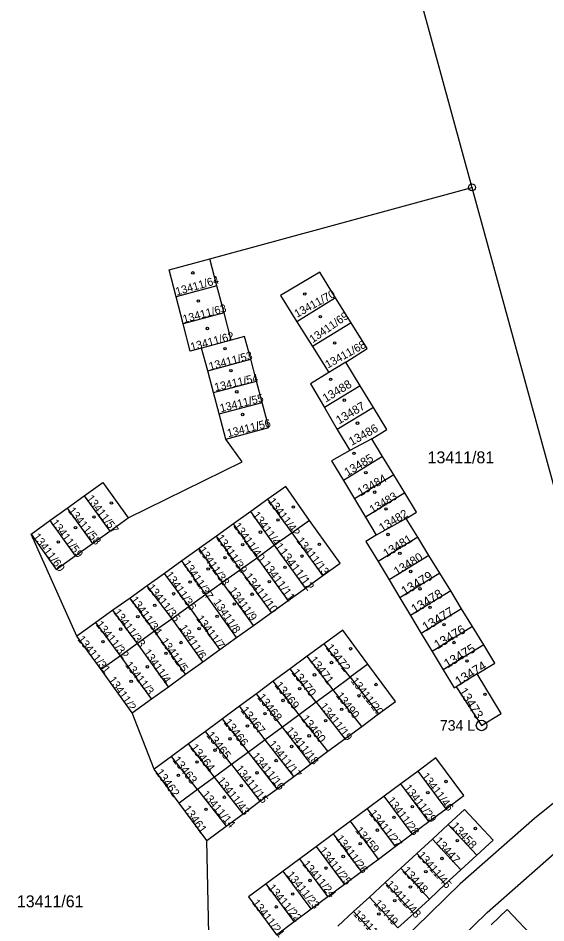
# Model space of a CAD drawing. Extents: x -821458 to -820266, y -1071458 to -1069826.
# Drawn here: x -820677.2 to -820602.1, y -1071105.6 to -1070976.8 of the extents above; entities that cross this region are included whole.
import ezdxf

# ---------------------------------------------------------------- set-up
doc = ezdxf.new("R2010")
doc.units = 0
for name, color, linetype in [('Vrstva 1', 7, 'Continuous'), ('Vrstva 13', 7, 'Continuous'), ('Vrstva 2', 7, 'Continuous'), ('Vrstva 5', 7, 'Continuous'), ('Vrstva 8', 7, 'Continuous')]:
    doc.layers.add(name, color=color, linetype=linetype)

msp = doc.modelspace()

# ---------------------------------------------------------------- linework, layer by layer
at = {"layer": 'Vrstva 1'}
for p, q in [((-820649.92, -1071011.03), (-820612.61, -1071000.86)), ((-820648.9, -1071014.88), (-820649.92, -1071011.03)), ((-820648.9, -1071014.88), (-820654.7, -1071016.44)), ((-820647.88, -1071018.73), (-820648.9, -1071014.88)), ((-820653.71, -1071020.3), (-820654.7, -1071016.44)), ((-820632.01, -1071016.56), (-820637.51, -1071019.98)), ((-820629.8, -1071020.12), (-820632.01, -1071016.56)), ((-820647.88, -1071018.73), (-820653.71, -1071020.3)), ((-820646.86, -1071022.59), (-820647.88, -1071018.73)), ((-820637.51, -1071019.98), (-820635.3, -1071023.53)), ((-820629.8, -1071020.12), (-820635.3, -1071023.53)), ((-820646.86, -1071022.59), (-820651.08, -1071023.73)), ((-820650.22, -1071026.97), (-820651.08, -1071023.73)), ((-820635.3, -1071023.53), (-820633, -1071027.22)), ((-820650.22, -1071026.97), (-820644.09, -1071025.33)), ((-820643.26, -1071028.43), (-820644.09, -1071025.33)), ((-820630.58, -1071025.73), (-820633, -1071027.22)), ((-820628.52, -1071029.09), (-820630.58, -1071025.73)), ((-820649.39, -1071030.06), (-820650.22, -1071026.97)), ((-820649.39, -1071030.06), (-820643.26, -1071028.43)), ((-820642.45, -1071031.47), (-820643.26, -1071028.43)), ((-820628.52, -1071029.09), (-820633.61, -1071032.21)), ((-820626.64, -1071032.17), (-820628.52, -1071029.09)), ((-820648.58, -1071033.1), (-820649.39, -1071030.06)), ((-820648.58, -1071033.1), (-820642.45, -1071031.47)), ((-820647.63, -1071036.68), (-820648.58, -1071033.1)), ((-820633.61, -1071032.21), (-820631.78, -1071035.32)), ((-820626.64, -1071032.17), (-820631.78, -1071035.32)), ((-820631.78, -1071035.32), (-820630.01, -1071038.31)), ((-820626.88, -1071036.63), (-820630.01, -1071038.31)), ((-820625.33, -1071039.17), (-820626.88, -1071036.63)), ((-820625.33, -1071039.17), (-820630.9, -1071042.58)), ((-820623.74, -1071041.77), (-820625.33, -1071039.17)), ((-820623.74, -1071041.77), (-820629.33, -1071045.19)), ((-820622.15, -1071044.36), (-820623.74, -1071041.77)), ((-820630.9, -1071042.58), (-820629.33, -1071045.19)), ((-820622.15, -1071044.36), (-820627.77, -1071047.8)), ((-820670.23, -1071046.52), (-820667.79, -1071044.76)), ((-820667.79, -1071044.76), (-820664.16, -1071049.8)), ((-820641.65, -1071045.26), (-820644.06, -1071046.98)), ((-820638.22, -1071050.05), (-820641.65, -1071045.26)), ((-820629.33, -1071045.19), (-820627.77, -1071047.8)), ((-820672.7, -1071048.29), (-820670.23, -1071046.52)), ((-820670.23, -1071046.52), (-820666.6, -1071051.55)), ((-820644.06, -1071046.98), (-820646.53, -1071048.75)), ((-820640.69, -1071051.81), (-820644.06, -1071046.98)), ((-820675.36, -1071050.21), (-820672.7, -1071048.29)), ((-820672.7, -1071048.29), (-820669.07, -1071053.32)), ((-820664.16, -1071049.8), (-820661.52, -1071047.91)), ((-820635.75, -1071048.27), (-820638.22, -1071050.05)), ((-820627.77, -1071047.8), (-820626.23, -1071050.37)), ((-820621.95, -1071047.97), (-820626.23, -1071050.37)), ((-820620.31, -1071050.66), (-820621.95, -1071047.97)), ((-820666.6, -1071051.55), (-820664.16, -1071049.8)), ((-820646.53, -1071048.75), (-820648.99, -1071050.52)), ((-820643.15, -1071053.58), (-820646.53, -1071048.75)), ((-820668.84, -1071064.74), (-820675.36, -1071050.21)), ((-820648.99, -1071050.52), (-820651.45, -1071052.28)), ((-820645.55, -1071055.3), (-820648.99, -1071050.52)), ((-820638.22, -1071050.05), (-820640.69, -1071051.81)), ((-820633.85, -1071056.13), (-820638.22, -1071050.05)), ((-820620.31, -1071050.66), (-820625.97, -1071054.13)), ((-820618.73, -1071053.25), (-820620.31, -1071050.66)), ((-820669.07, -1071053.32), (-820666.6, -1071051.55)), ((-820651.45, -1071052.28), (-820653.9, -1071054.04)), ((-820648.11, -1071057.12), (-820651.45, -1071052.28)), ((-820640.69, -1071051.81), (-820643.15, -1071053.58)), ((-820636.31, -1071057.9), (-820640.69, -1071051.81)), ((-820643.15, -1071053.58), (-820645.55, -1071055.3)), ((-820638.76, -1071059.67), (-820643.15, -1071053.58)), ((-820618.73, -1071053.25), (-820624.41, -1071056.73)), ((-820617.17, -1071055.79), (-820618.73, -1071053.25)), ((-820653.9, -1071054.04), (-820656.36, -1071055.8)), ((-820650.49, -1071058.83), (-820653.9, -1071054.04)), ((-820625.97, -1071054.13), (-820624.41, -1071056.73)), ((-820656.36, -1071055.8), (-820658.82, -1071057.56)), ((-820652.87, -1071060.54), (-820656.36, -1071055.8)), ((-820645.55, -1071055.3), (-820648.11, -1071057.12)), ((-820641.16, -1071061.39), (-820645.55, -1071055.3)), ((-820636.31, -1071057.9), (-820633.85, -1071056.13)), ((-820617.17, -1071055.79), (-820622.87, -1071059.28)), ((-820615.63, -1071058.31), (-820617.17, -1071055.79)), ((-820658.82, -1071057.56), (-820661.27, -1071059.32)), ((-820655.3, -1071062.28), (-820658.82, -1071057.56)), ((-820648.11, -1071057.12), (-820650.49, -1071058.83)), ((-820643.71, -1071063.22), (-820648.11, -1071057.12)), ((-820624.41, -1071056.73), (-820622.87, -1071059.28)), ((-820650.49, -1071058.83), (-820652.87, -1071060.54)), ((-820646.1, -1071064.94), (-820650.49, -1071058.83)), ((-820638.76, -1071059.67), (-820636.31, -1071057.9)), ((-820615.63, -1071058.31), (-820621.35, -1071061.81)), ((-820614.08, -1071060.84), (-820615.63, -1071058.31)), ((-820661.27, -1071059.32), (-820663.71, -1071061.06)), ((-820657.77, -1071064.05), (-820661.27, -1071059.32)), ((-820641.16, -1071061.39), (-820638.76, -1071059.67)), ((-820622.87, -1071059.28), (-820621.35, -1071061.81)), ((-820663.71, -1071061.06), (-820666.16, -1071062.82)), ((-820660.23, -1071065.81), (-820663.71, -1071061.06)), ((-820652.87, -1071060.54), (-820655.3, -1071062.28)), ((-820648.49, -1071066.66), (-820652.87, -1071060.54)), ((-820643.71, -1071063.22), (-820641.16, -1071061.39)), ((-820614.08, -1071060.84), (-820619.82, -1071064.35)), ((-820612.53, -1071063.38), (-820614.08, -1071060.84)), ((-820655.3, -1071062.28), (-820657.77, -1071064.05)), ((-820650.9, -1071068.4), (-820655.3, -1071062.28)), ((-820621.35, -1071061.81), (-820619.82, -1071064.35)), ((-820666.16, -1071062.82), (-820668.84, -1071064.74)), ((-820662.63, -1071067.53), (-820666.16, -1071062.82)), ((-820657.77, -1071064.05), (-820660.23, -1071065.81)), ((-820653.36, -1071070.17), (-820657.77, -1071064.05)), ((-820646.1, -1071064.94), (-820643.71, -1071063.22)), ((-820612.53, -1071063.38), (-820618.29, -1071066.91)), ((-820610.92, -1071066), (-820612.53, -1071063.38)), ((-820665.36, -1071069.48), (-820668.84, -1071064.74)), ((-820648.49, -1071066.66), (-820646.1, -1071064.94)), ((-820619.82, -1071064.35), (-820618.29, -1071066.91)), ((-820660.23, -1071065.81), (-820662.63, -1071067.53)), ((-820655.82, -1071071.94), (-820660.23, -1071065.81)), ((-820633.64, -1071065.84), (-820636.05, -1071067.61)), ((-820629.95, -1071070.59), (-820633.64, -1071065.84)), ((-820610.92, -1071066), (-820616.7, -1071069.54)), ((-820662.63, -1071067.53), (-820665.36, -1071069.48)), ((-820658.21, -1071073.66), (-820662.63, -1071067.53)), ((-820650.9, -1071068.4), (-820648.49, -1071066.66)), ((-820636.05, -1071067.61), (-820638.46, -1071069.39)), ((-820632.36, -1071072.37), (-820636.05, -1071067.61)), ((-820618.29, -1071066.91), (-820616.7, -1071069.54)), ((-820653.36, -1071070.17), (-820650.9, -1071068.4)), ((-820627.41, -1071068.72), (-820629.95, -1071070.59)), ((-820660.99, -1071075.66), (-820665.36, -1071069.48)), ((-820655.82, -1071071.94), (-820653.36, -1071070.17)), ((-820638.46, -1071069.39), (-820640.88, -1071071.17)), ((-820634.77, -1071074.14), (-820638.46, -1071069.39)), ((-820611.88, -1071070.12), (-820614.84, -1071071.94)), ((-820640.88, -1071071.17), (-820643.29, -1071072.95)), ((-820637.18, -1071075.92), (-820640.88, -1071071.17)), ((-820632.36, -1071072.37), (-820629.95, -1071070.59)), ((-820629.95, -1071070.59), (-820625.89, -1071075.82)), ((-820658.21, -1071073.66), (-820655.82, -1071071.94)), ((-820643.29, -1071072.95), (-820645.7, -1071074.73)), ((-820639.59, -1071077.7), (-820643.29, -1071072.95)), ((-820632.36, -1071072.37), (-820634.77, -1071074.14)), ((-820628.3, -1071077.59), (-820632.36, -1071072.37)), ((-820660.99, -1071075.66), (-820658.21, -1071073.66)), ((-820634.77, -1071074.14), (-820637.18, -1071075.92)), ((-820634.77, -1071074.14), (-820630.7, -1071079.36)), ((-820657.82, -1071083.67), (-820660.99, -1071075.66)), ((-820645.7, -1071074.73), (-820648.12, -1071076.51)), ((-820642.02, -1071079.48), (-820645.7, -1071074.73)), ((-820648.12, -1071076.51), (-820650.53, -1071078.3)), ((-820644.42, -1071081.25), (-820648.12, -1071076.51)), ((-820637.18, -1071075.92), (-820639.59, -1071077.7)), ((-820633.11, -1071081.13), (-820637.18, -1071075.92)), ((-820628.3, -1071077.59), (-820625.89, -1071075.82)), ((-820639.59, -1071077.7), (-820642.02, -1071079.48)), ((-820635.53, -1071082.91), (-820639.59, -1071077.7)), ((-820630.7, -1071079.36), (-820628.3, -1071077.59)), ((-820650.53, -1071078.3), (-820652.95, -1071080.08)), ((-820646.84, -1071083.03), (-820650.53, -1071078.3)), ((-820642.02, -1071079.48), (-820644.42, -1071081.25)), ((-820637.96, -1071084.7), (-820642.02, -1071079.48)), ((-820633.11, -1071081.13), (-820630.7, -1071079.36)), ((-820652.95, -1071080.08), (-820655.36, -1071081.86)), ((-820649.26, -1071084.81), (-820652.95, -1071080.08)), ((-820655.36, -1071081.86), (-820657.82, -1071083.67)), ((-820651.67, -1071086.59), (-820655.36, -1071081.86)), ((-820644.42, -1071081.25), (-820646.84, -1071083.03)), ((-820640.35, -1071086.46), (-820644.42, -1071081.25)), ((-820635.53, -1071082.91), (-820633.11, -1071081.13)), ((-820646.84, -1071083.03), (-820649.26, -1071084.81)), ((-820646.84, -1071083.03), (-820642.78, -1071088.25)), ((-820637.96, -1071084.7), (-820635.53, -1071082.91)), ((-820654.27, -1071088.51), (-820657.82, -1071083.67)), ((-820620.27, -1071083.95), (-820622.71, -1071085.76)), ((-820616.28, -1071089.31), (-820620.27, -1071083.95)), ((-820649.26, -1071084.81), (-820651.67, -1071086.59)), ((-820645.19, -1071090.02), (-820649.26, -1071084.81)), ((-820640.35, -1071086.46), (-820637.96, -1071084.7)), ((-820622.71, -1071085.76), (-820625.09, -1071087.53)), ((-820618.72, -1071091.13), (-820622.71, -1071085.76)), ((-820651.67, -1071086.59), (-820654.27, -1071088.51)), ((-820651.67, -1071086.59), (-820647.61, -1071091.8)), ((-820642.78, -1071088.25), (-820640.35, -1071086.46)), ((-820650.36, -1071093.83), (-820654.27, -1071088.51)), ((-820645.19, -1071090.02), (-820642.78, -1071088.25)), ((-820625.09, -1071087.53), (-820627.5, -1071089.32)), ((-820621.11, -1071092.9), (-820625.09, -1071087.53)), ((-820627.5, -1071089.32), (-820629.91, -1071091.1)), ((-820627.5, -1071089.32), (-820623.52, -1071094.68)), ((-820618.72, -1071091.13), (-820616.28, -1071089.31)), ((-820647.61, -1071091.8), (-820645.19, -1071090.02)), ((-820629.91, -1071091.1), (-820632.3, -1071092.87)), ((-820625.93, -1071096.47), (-820629.91, -1071091.1)), ((-820650.36, -1071093.83), (-820647.61, -1071091.8)), ((-820621.11, -1071092.9), (-820618.72, -1071091.13)), ((-820615.99, -1071091.55), (-820618.24, -1071093.62)), ((-820611.92, -1071095.94), (-820615.99, -1071091.55)), ((-820632.3, -1071092.87), (-820634.72, -1071094.67)), ((-820628.31, -1071098.24), (-820632.3, -1071092.87)), ((-820623.52, -1071094.68), (-820621.11, -1071092.9)), ((-820618.24, -1071093.62), (-820620.47, -1071095.69)), ((-820614.17, -1071098.01), (-820618.24, -1071093.62)), ((-820634.72, -1071094.67), (-820637.09, -1071096.43)), ((-820630.73, -1071100.04), (-820634.72, -1071094.67)), ((-820625.93, -1071096.47), (-820623.52, -1071094.68)), ((-820620.47, -1071095.69), (-820622.74, -1071097.77)), ((-820620.47, -1071095.69), (-820616.4, -1071100.07)), ((-820614.17, -1071098.01), (-820611.92, -1071095.94)), ((-820637.09, -1071096.43), (-820639.49, -1071098.21)), ((-820633.1, -1071101.8), (-820637.09, -1071096.43)), ((-820628.31, -1071098.24), (-820625.93, -1071096.47)), ((-820639.49, -1071098.21), (-820641.91, -1071100.01)), ((-820635.49, -1071103.58), (-820639.49, -1071098.21)), ((-820630.73, -1071100.04), (-820628.31, -1071098.24)), ((-820622.74, -1071097.77), (-820624.97, -1071099.83)), ((-820618.67, -1071102.16), (-820622.74, -1071097.77)), ((-820616.4, -1071100.07), (-820614.17, -1071098.01)), ((-820637.92, -1071105.38), (-820641.91, -1071100.01)), ((-820633.1, -1071101.8), (-820630.73, -1071100.04)), ((-820624.97, -1071099.83), (-820627.21, -1071101.9)), ((-820624.97, -1071099.83), (-820620.9, -1071104.22)), ((-820618.67, -1071102.16), (-820616.4, -1071100.07)), ((-820635.49, -1071103.58), (-820633.1, -1071101.8)), ((-820627.21, -1071101.9), (-820629.45, -1071103.96)), ((-820623.14, -1071106.28), (-820627.21, -1071101.9)), ((-820620.9, -1071104.22), (-820618.67, -1071102.16)), ((-820637.92, -1071105.38), (-820635.49, -1071103.58)), ((-820629.45, -1071103.96), (-820631.7, -1071106.04)), ((-820625.38, -1071108.35), (-820629.45, -1071103.96)), ((-820623.14, -1071106.28), (-820620.9, -1071104.22))]:
    msp.add_line(p, q, dxfattribs=at)
for points in [[(-820639.81, -1070901.39), (-820638.53, -1070906.11), (-820612.61, -1071000.86)], [(-820612.61, -1071000.86), (-820596.7, -1071059), (-820571.9, -1071098.21)], [(-820654.7, -1071016.44), (-820655.7, -1071012.58), (-820649.92, -1071011.03)], [(-820632.01, -1071016.56), (-820634.28, -1071012.91), (-820639.84, -1071016.23), (-820637.51, -1071019.98)], [(-820630.58, -1071025.73), (-820627.53, -1071023.78), (-820629.8, -1071020.12)], [(-820651.08, -1071023.73), (-820652.71, -1071024.15), (-820653.71, -1071020.3)], [(-820644.09, -1071025.33), (-820644.96, -1071022.08), (-820646.86, -1071022.59)], [(-820633, -1071027.22), (-820635.6, -1071028.82), (-820633.61, -1071032.21)], [(-820647.63, -1071036.68), (-820641.5, -1071035.04), (-820642.45, -1071031.47)], [(-820626.88, -1071036.63), (-820624.72, -1071035.31), (-820626.64, -1071032.17)], [(-820661.52, -1071047.91), (-820645.33, -1071039.94), (-820647.63, -1071036.68)], [(-820630.01, -1071038.31), (-820632.58, -1071039.77), (-820630.9, -1071042.58)], [(-820667.79, -1071044.76), (-820665.15, -1071042.86), (-820661.52, -1071047.91)], [(-820635.75, -1071048.27), (-820639.12, -1071043.44), (-820641.65, -1071045.26)], [(-820621.95, -1071047.97), (-820620.49, -1071047.08), (-820622.15, -1071044.36)], [(-820633.85, -1071056.13), (-820631.36, -1071054.34), (-820635.75, -1071048.27)], [(-820675.36, -1071050.21), (-820671.77, -1071055.26), (-820669.07, -1071053.32)], [(-820626.23, -1071050.37), (-820627.7, -1071051.26), (-820625.97, -1071054.13)], [(-820627.41, -1071068.72), (-820630.98, -1071063.87), (-820633.64, -1071065.84)], [(-820611.88, -1071070.12), (-820609.35, -1071068.57), (-820610.92, -1071066)], [(-820625.89, -1071075.82), (-820623.49, -1071074.05), (-820627.41, -1071068.72)], [(-820616.7, -1071069.54), (-820615.15, -1071072.12), (-820614.84, -1071071.94)], [(-820614.84, -1071071.94), (-820611.24, -1071077.45), (-820608.44, -1071075.74), (-820611.88, -1071070.12)], [(-820616.28, -1071089.31), (-820613.74, -1071087.42), (-820617.73, -1071082.07), (-820620.27, -1071083.95)], [(-820611.92, -1071095.94), (-820609.6, -1071093.8), (-820613.67, -1071089.41), (-820615.99, -1071091.55)], [(-820637.33, -1071155.3), (-820640.67, -1071151.76), (-820642.44, -1071140.23), (-820649.73, -1071122.67), (-820650.36, -1071093.83)], [(-820641.91, -1071100.01), (-820644.43, -1071101.87), (-820640.43, -1071107.25), (-820637.92, -1071105.38)], [(-820605.79, -1071110.2), (-820603.47, -1071108.04), (-820607.58, -1071103.67), (-820609.89, -1071105.82)]]:
    msp.add_lwpolyline(points, dxfattribs=at)
at = {"layer": 'Vrstva 13'}
msp.add_lwpolyline([(-820675.1, -1071148.28), (-820672.81, -1071153.44), (-820638.57, -1071131.55), (-820610.44, -1071104.1), (-820600.08, -1071094.97), (-820582.77, -1071081.03), (-820585.78, -1071076.26), (-820603.68, -1071090.69), (-820614.26, -1071100), (-820642.01, -1071127.07)], close=True, dxfattribs=at)
at = {"layer": 'Vrstva 5'}
for centre in [(-820652.34, -1071013.03), (-820636.4, -1071016.04), (-820651.56, -1071017.04), (-820634.18, -1071019.25), (-820650.26, -1071020.95), (-820632.15, -1071023.01), (-820647.75, -1071023.81), (-820646.92, -1071026.95), (-820632.72, -1071028.18), (-820646.08, -1071029.96), (-820630.78, -1071031.15), (-820645.25, -1071033.19), (-820628.9, -1071034.42), (-820629.4, -1071038.73), (-820627.71, -1071041.48), (-820626.45, -1071044.24), (-820663.92, -1071045.78), (-820638.02, -1071046.36), (-820624.83, -1071046.64), (-820666.41, -1071047.77), (-820640.2, -1071048.2), (-820669.04, -1071049.29), (-820642.71, -1071049.94), (-820671.49, -1071051.33), (-820624.55, -1071050.27), (-820645.23, -1071051.73), (-820634.32, -1071051.68), (-820647.75, -1071053.57), (-820636.81, -1071053.35), (-820622.87, -1071052.96), (-820650.15, -1071055.19), (-820639.21, -1071054.95), (-820621.32, -1071055.54), (-820652.72, -1071057.04), (-820641.45, -1071056.98), (-820655.07, -1071058.71), (-820643.89, -1071058.77), (-820619.99, -1071058.01), (-820657.75, -1071060.34), (-820646.43, -1071060.16), (-820618.57, -1071060.63), (-820660.16, -1071061.96), (-820648.88, -1071061.91), (-820662.62, -1071063.75), (-820651.44, -1071063.69), (-820616.57, -1071063.1), (-820665.13, -1071065.53), (-820654.01, -1071065.65), (-820629.87, -1071066.54), (-820615.16, -1071065.65), (-820656.16, -1071067.18), (-820658.81, -1071069.11), (-820632.6, -1071068.5), (-820613.32, -1071068.27), (-820635.02, -1071070.25), (-820661.11, -1071071.18), (-820626.25, -1071071.63), (-820637.14, -1071072.21), (-820628.69, -1071073.23), (-820610.75, -1071073.02), (-820639.49, -1071073.9), (-820642.06, -1071075.79), (-820631.14, -1071075.16), (-820633.43, -1071076.77), (-820644.56, -1071077.54), (-820647.05, -1071079.36), (-820635.78, -1071078.93), (-820649.17, -1071080.97), (-820638.28, -1071080.45), (-820651.74, -1071082.65), (-820640.48, -1071082.45), (-820654.39, -1071084.54), (-820643.19, -1071084.2), (-820645.42, -1071086.03), (-820616.29, -1071085.43), (-820618.89, -1071087.03), (-820647.84, -1071087.67), (-820650.46, -1071089.38), (-820621.1, -1071089.01), (-820623.71, -1071090.52), (-820626.06, -1071092.36), (-820612.11, -1071092.12), (-820614.69, -1071093.86), (-820628.51, -1071094.28), (-820630.93, -1071096.11), (-820616.88, -1071096.39), (-820633.37, -1071097.76), (-820619.17, -1071098.28), (-820635.65, -1071099.52), (-820638.12, -1071101.45), (-820621.36, -1071100.46), (-820623.59, -1071102.41), (-820640.46, -1071103.28), (-820625.86, -1071104.28)]:
    msp.add_circle(centre, 0.175, dxfattribs=at)
at = {"layer": 'Vrstva 8'}
for centre, radius in [((-820612.61, -1071000.86), 0.5), ((-820612.61, -1071000.86), 0.0303), ((-820611.24, -1071077.45), 0.75), ((-820611.24, -1071077.45), 0.03)]:
    msp.add_circle(centre, radius, dxfattribs=at)

# ---------------------------------------------------------------- texts
at = {"layer": 'Vrstva 2'}
for s, height, rotation, p in [('13411/64', 1.139, 16, (-820654.62, -1071016.26)), ('13411/70', 1.139, 29, (-820637.5, -1071019.44)), ('13411/63', 1.139, 15, (-820653.6, -1071020.18)), ('13411/69', 1.139, 35, (-820635.26, -1071023.06)), ('13411/62', 1.139, 15, (-820652.51, -1071024.14)), ('13411/68', 1.139, 29, (-820633.12, -1071026.66)), ('13411/53', 1.139, 15, (-820649.89, -1071026.91)), ('13411/54', 1.139, 13, (-820649.13, -1071029.89)), ('13488', 1.2, 31, (-820633.42, -1071031.5)), ('13411/55', 1.139, 14, (-820648.34, -1071032.87)), ('13487', 1.2, 31, (-820631.52, -1071034.62)), ('13411/56', 1.139, 14, (-820647.31, -1071036.43)), ('13486', 1.2, 29, (-820629.73, -1071037.67)), ('13485', 1.2, 31, (-820630.33, -1071042.03)), ('13484', 1.2, 30, (-820628.48, -1071044.88)), ('13411/57', 1.139, 307, (-820667.54, -1071045.15)), ('13483', 1.139, 31, (-820626.76, -1071047.3)), ('13411/42', 1.139, 307, (-820641.69, -1071045.57)), ('13411/58', 1.139, 309, (-820670.17, -1071046.93)), ('13411/41', 1.139, 306, (-820643.92, -1071047.51)), ('13482', 1.2, 31, (-820625.4, -1071049.94)), ('13411/59', 1.139, 307, (-820672.58, -1071048.62)), ('13411/40', 1.139, 306, (-820646.62, -1071049.08)), ('13411/60', 1.139, 307, (-820675.17, -1071050.6)), ('13411/39', 1.139, 305, (-820649.06, -1071050.75)), ('13411/13', 1.139, 308, (-820637.64, -1071051.18)), ('13481', 1.2, 32, (-820624.78, -1071053.58)), ('13411/38', 1.139, 305, (-820651.61, -1071052.49)), ('13411/12', 1.26, 307, (-820640.19, -1071052.78)), ('13480', 1.2, 32, (-820623.27, -1071056.15)), ('13411/37', 1.139, 304, (-820653.82, -1071054.37)), ('13411/11', 1.185, 306, (-820642.51, -1071054.53)), ('13411/36', 1.139, 305, (-820656.31, -1071056)), ('13411/10', 1.195, 307, (-820645.08, -1071056.29)), ('13479', 1.3, 31, (-820622.19, -1071059.02)), ('13411/35', 1.139, 309, (-820658.88, -1071057.87)), ('13411/9', 1.139, 306, (-820647.25, -1071058.24)), ('13478', 1.3, 31, (-820620.77, -1071061.57)), ('13411/34', 1.139, 306, (-820661.28, -1071059.57)), ('13411/8', 1.139, 304, (-820649.47, -1071059.91)), ('13411/33', 1.139, 307, (-820663.7, -1071061.37)), ('13477', 1.3, 31, (-820619.19, -1071064.11)), ('13411/32', 1.139, 309, (-820666.2, -1071063.12)), ('13411/7', 1.139, 307, (-820651.91, -1071062.27)), ('13411/6', 1.139, 303, (-820654.29, -1071063.53)), ('13476', 1.3, 31, (-820617.52, -1071066.65)), ('13411/31', 1.139, 309, (-820668.82, -1071065.23)), ('13411/5', 1.139, 305, (-820656.98, -1071065.47)), ('13411/4', 1.139, 305, (-820659.44, -1071067.06)), ('13472', 1.2, 308, (-820633.48, -1071066.41)), ('13475', 1.3, 31, (-820616.11, -1071069.35)), ('13471', 1.2, 307, (-820635.82, -1071068.14)), ('13411/3', 1.139, 308, (-820662.04, -1071068.87)), ('13474', 1.3, 32, (-820614.5, -1071071.86)), ('13470', 1.2, 308, (-820638.36, -1071069.94)), ('13411/2', 1.139, 305, (-820664.39, -1071070.96)), ('13469', 1.2, 308, (-820640.75, -1071071.77)), ('13411/20', 1.139, 308, (-820629.91, -1071071.13)), ('13468', 1.2, 308, (-820643.22, -1071073.48)), ('13490', 1.139, 308, (-820632.02, -1071073.24)), ('13473', 1.3, 302, (-820614.55, -1071072.57)), ('13411/19', 1.139, 308, (-820634.33, -1071074.76)), ('13467', 1.2, 308, (-820645.61, -1071075.31)), ('13466', 1.2, 308, (-820648.02, -1071077.04)), ('13460', 1.2, 308, (-820636.99, -1071076.52)), ('13411/18', 1.139, 309, (-820639.17, -1071078.21)), ('13465', 1.2, 308, (-820650.48, -1071078.86)), ('13464', 1.2, 308, (-820652.78, -1071080.63)), ('13411/17', 1.139, 309, (-820641.64, -1071080.14)), ('13463', 1.2, 308, (-820655.29, -1071082.4)), ('13411/16', 1.139, 309, (-820644, -1071081.83)), ('13411/15', 1.139, 308, (-820646.33, -1071083.65)), ('13462', 1.2, 306, (-820657.7, -1071084.16)), ('13411/46', 1.139, 307, (-820619.84, -1071084.69)), ('13411/43', 1.139, 308, (-820648.93, -1071085.32)), ('13411/29', 1.139, 308, (-820622.34, -1071086.37)), ('13411/14', 1.139, 310, (-820651.13, -1071087.3)), ('13411/28', 1.139, 307, (-820624.73, -1071088.14)), ('13461', 1.2, 306, (-820653.82, -1071089.33)), ('13411/27', 1.139, 309, (-820627.32, -1071089.99)), ('13459', 1.139, 310, (-820629.28, -1071092.45)), ('13458', 1.2, 312, (-820615.68, -1071091.83)), ('13411/26', 1.139, 307, (-820632.04, -1071093.56)), ('13447', 1.2, 312, (-820618.05, -1071093.96)), ('13411/25', 1.139, 308, (-820634.44, -1071095.27)), ('13411/45', 1.139, 311, (-820620.41, -1071095.98)), ('13411/24', 1.139, 310, (-820636.82, -1071097.22)), ('13411/23', 1.139, 309, (-820639.04, -1071098.75)), ('13448', 1.2, 312, (-820622.6, -1071098.18)), ('13411/22', 1.139, 310, (-820641.71, -1071100.61)), ('13411/48', 1.167, 312, (-820624.96, -1071100.15)), ('13411/21', 1.139, 308, (-820643.96, -1071102.73)), ('13449', 1.139, 312, (-820626.66, -1071102.85)), ('13411/50', 1.139, 313, (-820629.57, -1071104.34))]:
    msp.add_text(s, height=height, rotation=rotation, dxfattribs=at).set_placement(p)
for s, p in [('13411/81', (-820618.92, -1071040.14)), ('13411/61', (-820677.38, -1071103.34))]:
    msp.add_text(s, height=1.7, dxfattribs=at).set_placement(p)
at = {"layer": 'Vrstva 8'}
msp.add_text('734 L', height=1.5, dxfattribs=at).set_placement((-820617.17, -1071078.2))

doc.saveas('drawing.dxf')
